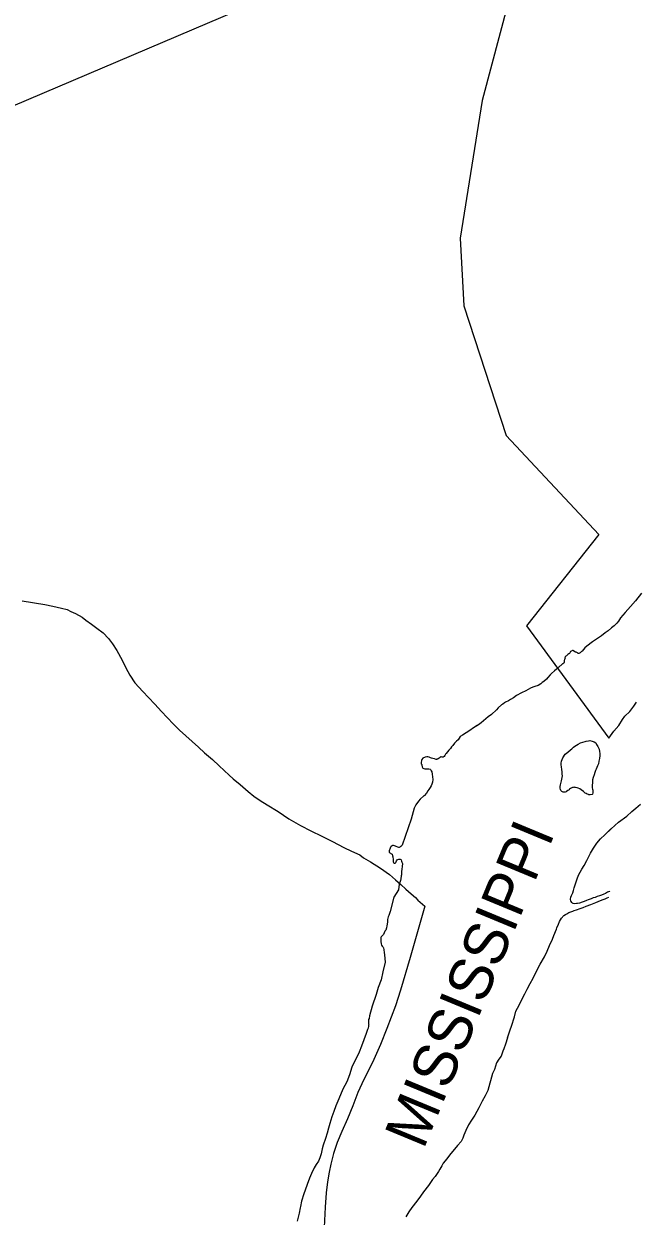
# Model space of a CAD drawing. Extents: x -117616 to 64730, y 54117 to 789866.
# Drawn here: x 62107.1 to 62196.9, y 55691.7 to 55866.6 of the extents above; entities that cross this region are included whole.
import ezdxf

# ---------------------------------------------------------------- set-up
doc = ezdxf.new("R2010")
doc.units = 0
for name, color, linetype in [('3', 7, 'Continuous'), ('9', 7, 'Continuous'), ('R_Draft', 7, 'Continuous')]:
    doc.layers.add(name, color=color, linetype=linetype)

msp = doc.modelspace()

# ---------------------------------------------------------------- linework, layer by layer
at = {"layer": '3'}
for points in [[(62179.37, 55874.54), (62174.3, 55855.4), (62171.05, 55835.19), (62171.61, 55825.27), (62177.79, 55806.26), (62191.41, 55791.73), (62180.77, 55778.33), (62192.85, 55761.85), (62193.58, 55762.86), (62194.3, 55763.69), (62194.87, 55764.57), (62195.19, 55765.06), (62195.93, 55765.76), (62196.51, 55766.52), (62196.91, 55767.09)], [(62106.85, 55781.99), (62110.15, 55781.44), (62111.35, 55781.19), (62112.64, 55780.92), (62113.44, 55780.69), (62113.99, 55780.42), (62114.67, 55780.11), (62115.66, 55779.58), (62116.2, 55779.16), (62117, 55778.55), (62117.82, 55777.97), (62118.72, 55777.27), (62119.52, 55776.46), (62120.08, 55775.67), (62120.73, 55774.68), (62121.5, 55773.29), (62122.03, 55772.14), (62122.62, 55771.07), (62123.38, 55769.97), (62124.54, 55768.67), (62125.35, 55767.82), (62126.31, 55766.84), (62127.3, 55765.76), (62128.12, 55764.86), (62129.04, 55763.88), (62129.92, 55763), (62132.68, 55760.5), (62133.59, 55759.67), (62134.76, 55758.69), (62135.73, 55757.79), (62137.19, 55756.42), (62137.8, 55755.87), (62138.8, 55755.03), (62139.97, 55754.02), (62140.83, 55753.33), (62141.73, 55752.69), (62142.76, 55752.05), (62144.4, 55751.05), (62145.95, 55749.99), (62147.64, 55749), (62149.16, 55748.23), (62150.8, 55747.45), (62152.34, 55746.69), (62154.02, 55745.81), (62155.15, 55745.27), (62156.33, 55744.69), (62156.89, 55744.28), (62157.93, 55743.68), (62159.37, 55742.76), (62160.68, 55741.83), (62161.59, 55741.03), (62162.37, 55740.34), (62163.12, 55739.68), (62163.87, 55739.01), (62164.5, 55738.47), (62164.87, 55738.04), (62165.87, 55737.16), (62163.72, 55729.66), (62162.33, 55724.87), (62161.6, 55722.56), (62160.29, 55719.22), (62159.36, 55716.9)], [(62159.36, 55716.9), (62158.22, 55714.26), (62156.92, 55711.77), (62156.04, 55709.83), (62155.34, 55707.88), (62154.52, 55705.97), (62153.72, 55704.11), (62153.04, 55702.5), (62152.49, 55700.89), (62152.1, 55699.34), (62151.85, 55698.16), (62151.62, 55696.73), (62151.43, 55695.1), (62151.25, 55693), (62151.11, 55690.09)]]:
    msp.add_lwpolyline(points, dxfattribs=at)
at = {"layer": '9'}
for points in [[(62197.65, 55783.09), (62196.78, 55781.99), (62196.03, 55781.13), (62195.27, 55780.27), (62194.59, 55779.49), (62194.26, 55779.02), (62194.01, 55778.69), (62193.92, 55778.6), (62193.63, 55778.31), (62193.24, 55778.03), (62192.77, 55777.6), (62192.32, 55777.28), (62191.76, 55776.86), (62191.04, 55776.36), (62190.48, 55775.97), (62189.62, 55775.35), (62189.36, 55775.09), (62189.14, 55774.83), (62188.95, 55774.62), (62188.87, 55774.55), (62188.79, 55774.48), (62188.67, 55774.37), (62188.48, 55774.26), (62188.45, 55774.26), (62188.37, 55774.27), (62188.33, 55774.27), (62188.24, 55774.34), (62188.14, 55774.4), (62188.07, 55774.43), (62187.98, 55774.46), (62187.87, 55774.52), (62187.68, 55774.63), (62187.61, 55774.67), (62187.56, 55774.68), (62187.55, 55774.69), (62187.43, 55774.64), (62187.36, 55774.61), (62187.24, 55774.54), (62187.2, 55774.46), (62187.13, 55774.33), (62187.08, 55774.26), (62187.07, 55774.26), (62186.99, 55774.2), (62186.86, 55774.1), (62186.74, 55774), (62186.63, 55773.92), (62186.53, 55773.84), (62186.43, 55773.75), (62186.42, 55773.67), (62186.43, 55773.6), (62186.42, 55773.47), (62186.38, 55773.37), (62186.35, 55773.31), (62186.32, 55773.24), (62186.32, 55773.16), (62186.31, 55773.06), (62186.29, 55772.96), (62186.25, 55772.83), (62186.13, 55772.75), (62186.01, 55772.68), (62185.54, 55772.26), (62185.42, 55772.18), (62185.2, 55771.97), (62184.89, 55771.71), (62184.45, 55771.3), (62184.27, 55771.1), (62183.92, 55770.71), (62183.7, 55770.49), (62183.34, 55770.16), (62183.1, 55770)], [(62183.1, 55770), (62182.88, 55769.82), (62182.5, 55769.57), (62182.02, 55769.42), (62181.73, 55769.32), (62181.36, 55769.17), (62180.67, 55768.79), (62180.07, 55768.5), (62179.34, 55768.08), (62178.86, 55767.77), (62178.42, 55767.49), (62178.13, 55767.33), (62177.73, 55767.11), (62177.54, 55767), (62177.32, 55766.83), (62177.14, 55766.7), (62176.64, 55766.28), (62176.38, 55766.01), (62175.66, 55765.32), (62175.19, 55764.94), (62174.15, 55764.09), (62173.77, 55763.78), (62173.01, 55763.37), (62172.46, 55762.96), (62171.38, 55762.27), (62171.06, 55762.08), (62170.77, 55761.59), (62170.54, 55761.4), (62170.25, 55761.11), (62169.98, 55760.78), (62169.79, 55760.54), (62169.62, 55760.34), (62169.42, 55760.08), (62169.21, 55759.82), (62168.99, 55759.59), (62168.9, 55759.46), (62168.79, 55759.27), (62168.7, 55759.15), (62168.57, 55759.06), (62168.51, 55759.05), (62168.42, 55759.06), (62168.27, 55759.07), (62168.26, 55759.07), (62168.22, 55759.07), (62168.19, 55759.04), (62168.14, 55759.02), (62168.06, 55758.98), (62168.01, 55758.96), (62167.97, 55758.91), (62167.82, 55758.8), (62167.75, 55758.77), (62167.66, 55758.73), (62167.58, 55758.69), (62167.54, 55758.72), (62167.32, 55758.8), (62167.03, 55758.86), (62166.84, 55758.91), (62166.69, 55758.97), (62166.53, 55759.05), (62166.32, 55759.1), (62166.19, 55759.09), (62165.95, 55759.05), (62165.81, 55759), (62165.67, 55758.94), (62165.61, 55758.89), (62165.45, 55758.7), (62165.38, 55758.54), (62165.34, 55758.25), (62165.35, 55758.09), (62165.42, 55757.95), (62165.43, 55757.82), (62165.47, 55757.72), (62165.51, 55757.62), (62165.55, 55757.51), (62165.61, 55757.41), (62165.74, 55757.36), (62165.87, 55757.33), (62166.05, 55757.32), (62166.19, 55757.31), (62166.32, 55757.31), (62166.47, 55757.32), (62166.66, 55757.29), (62166.73, 55757.22), (62166.77, 55757.15), (62166.82, 55757.05), (62166.9, 55756.88), (62166.94, 55756.54), (62166.99, 55756.14), (62167.04, 55755.77), (62167.02, 55755.38), (62166.93, 55755.07), (62166.81, 55754.86), (62166.65, 55754.61), (62166.49, 55754.3), (62166.34, 55754.08), (62166.12, 55753.76), (62165.77, 55753.37), (62165.75, 55753.35), (62165.22, 55752.89), (62164.94, 55752.59), (62164.54, 55752.06)], [(62173.57, 55763.67), (62173.01, 55763.37), (62172.46, 55762.96), (62171.38, 55762.27), (62171.06, 55762.08), (62170.77, 55761.59), (62170.54, 55761.4), (62170.25, 55761.11), (62169.98, 55760.78), (62169.79, 55760.54), (62169.62, 55760.34), (62169.42, 55760.08), (62169.21, 55759.82), (62168.99, 55759.59), (62168.9, 55759.46), (62168.79, 55759.27), (62168.7, 55759.15), (62168.57, 55759.06), (62168.51, 55759.05), (62168.42, 55759.06), (62168.27, 55759.07), (62168.26, 55759.07), (62168.22, 55759.07), (62168.19, 55759.04), (62168.14, 55759.02), (62168.06, 55758.98), (62168.01, 55758.96), (62167.97, 55758.91), (62167.82, 55758.8), (62167.75, 55758.77), (62167.66, 55758.73), (62167.58, 55758.69), (62167.54, 55758.72), (62167.32, 55758.8), (62167.03, 55758.86), (62166.84, 55758.91), (62166.69, 55758.97), (62166.53, 55759.05), (62166.32, 55759.1), (62166.19, 55759.09), (62165.95, 55759.05), (62165.81, 55759), (62165.67, 55758.94), (62165.61, 55758.89), (62165.45, 55758.7), (62165.38, 55758.54), (62165.34, 55758.25), (62165.35, 55758.09), (62165.42, 55757.95), (62165.43, 55757.82), (62165.47, 55757.72), (62165.51, 55757.62), (62165.55, 55757.51), (62165.61, 55757.41), (62165.74, 55757.36), (62165.87, 55757.33), (62166.05, 55757.32), (62166.19, 55757.31), (62166.32, 55757.31), (62166.47, 55757.32), (62166.66, 55757.29), (62166.73, 55757.22), (62166.77, 55757.15), (62166.82, 55757.05), (62166.9, 55756.88), (62166.94, 55756.54), (62166.99, 55756.14), (62167.04, 55755.77), (62167.02, 55755.38), (62166.93, 55755.07), (62166.81, 55754.86), (62166.65, 55754.61), (62166.49, 55754.3), (62166.34, 55754.08), (62166.12, 55753.76), (62165.77, 55753.37), (62165.75, 55753.35), (62165.22, 55752.89), (62164.94, 55752.59), (62164.54, 55752.06)], [(62185.86, 55757.95), (62185.85, 55758.18), (62185.92, 55758.45), (62186.1, 55758.95), (62186.45, 55759.48), (62186.85, 55759.79), (62187.25, 55760.12), (62187.41, 55760.27), (62187.7, 55760.49), (62187.89, 55760.65), (62188.38, 55760.96), (62188.7, 55761.14), (62189.02, 55761.25), (62189.38, 55761.35), (62189.51, 55761.38), (62189.87, 55761.46), (62190.08, 55761.47), (62190.39, 55761.41), (62190.72, 55761.3), (62190.97, 55761.15), (62191.07, 55760.9), (62191.25, 55760.61), (62191.42, 55760.24), (62191.51, 55759.89), (62191.55, 55759.6), (62191.53, 55759.28), (62191.47, 55758.86), (62191.4, 55758.45), (62191.32, 55758.09), (62191.19, 55757.76), (62190.99, 55757.3), (62190.9, 55757.09), (62190.79, 55756.78), (62190.7, 55756.44), (62190.56, 55756.07), (62190.48, 55755.7), (62190.45, 55755.31), (62190.43, 55754.89), (62190.43, 55754.55), (62190.45, 55754.36), (62190.49, 55754.2), (62190.53, 55753.99), (62190.53, 55753.82), (62190.47, 55753.63), (62190.39, 55753.57), (62190.14, 55753.53), (62189.92, 55753.54), (62189.87, 55753.55), (62189.67, 55753.62), (62189.51, 55753.69), (62189.37, 55753.77), (62189.28, 55753.87), (62189.16, 55754), (62188.81, 55754.27), (62188.61, 55754.38), (62188.36, 55754.49), (62188.2, 55754.53), (62187.96, 55754.59), (62187.85, 55754.61), (62187.77, 55754.62), (62187.65, 55754.59), (62187.51, 55754.57), (62187.45, 55754.54), (62187.33, 55754.5), (62187.25, 55754.45), (62187.11, 55754.34), (62187.02, 55754.24), (62186.86, 55754.15), (62186.67, 55754.02), (62186.58, 55753.97), (62186.45, 55753.93), (62186.28, 55753.91), (62186.16, 55753.93), (62185.96, 55754.02), (62185.88, 55754.09), (62185.82, 55754.17), (62185.78, 55754.29), (62185.72, 55754.51), (62185.71, 55754.72), (62185.77, 55754.98), (62185.82, 55755.2)], [(62185.82, 55755.2), (62185.92, 55755.55), (62185.98, 55755.82), (62186.04, 55756.3), (62186.03, 55756.53), (62186.02, 55756.83), (62185.97, 55757.27), (62185.93, 55757.56), (62185.86, 55757.95)], [(62164.54, 55752.06), (62164.34, 55751.55), (62163.88, 55749.93), (62162.54, 55746.13), (62162.47, 55746.05), (62162.36, 55745.95), (62162.33, 55745.92), (62162.28, 55745.87), (62162.2, 55745.82), (62162.12, 55745.8), (62162.05, 55745.8), (62161.91, 55745.85), (62161.69, 55745.93), (62161.57, 55745.98), (62161.41, 55746.03), (62161.28, 55746.08), (62161.16, 55746.07), (62161.08, 55746.03), (62160.93, 55745.95), (62160.84, 55745.84), (62160.78, 55745.69), (62160.73, 55745.55), (62160.69, 55745.43), (62160.65, 55745.32), (62160.63, 55745.2), (62160.66, 55745.11), (62160.77, 55745.02), (62160.84, 55744.97), (62160.9, 55744.93), (62161, 55744.85), (62161.07, 55744.8), (62161.12, 55744.59), (62161.18, 55744.44), (62161.2, 55744.3), (62161.24, 55744.13), (62161.25, 55744.01), (62161.25, 55743.89), (62161.24, 55743.79), (62161.26, 55743.68), (62161.3, 55743.57), (62161.32, 55743.52), (62161.35, 55743.48), (62161.4, 55743.48), (62161.47, 55743.47), (62161.52, 55743.5), (62161.56, 55743.55), (62161.61, 55743.61), (62161.66, 55743.69), (62161.73, 55743.81), (62161.83, 55743.96), (62161.93, 55744.04), (62162.05, 55744.1), (62162.15, 55744.09), (62162.26, 55744.08), (62162.34, 55744.03), (62162.39, 55743.96), (62162.44, 55743.8), (62162.53, 55743.63), (62162.59, 55743.43), (62162.58, 55742.98), (62162.53, 55742.6), (62162.48, 55742.27), (62162.46, 55741.79), (62162.42, 55741.63), (62162.34, 55741.21), (62162.32, 55740.95), (62162.27, 55740.79), (62162.17, 55740.54), (62162.1, 55740.41), (62162, 55739.59), (62161.32, 55738.5), (62160.8, 55736.42), (62160.62, 55735.82), (62160.53, 55735.61), (62160.43, 55735.21), (62160.39, 55734.89), (62160.36, 55734.54), (62160.33, 55734.3), (62160.25, 55733.98), (62160.14, 55733.66), (62160.03, 55733.5), (62159.93, 55733.26), (62159.81, 55733.04), (62159.71, 55732.93), (62159.62, 55732.83), (62159.5, 55732.67), (62159.44, 55732.57), (62159.41, 55732.49), (62159.42, 55732.25), (62159.42, 55731.99), (62159.49, 55731.67), (62159.55, 55731.47), (62159.63, 55731.3), (62159.76, 55731.16), (62159.84, 55731.05), (62159.88, 55730.78), (62159.93, 55730.36), (62159.96, 55730.06), (62160.06, 55728.97), (62159.74, 55727.55), (62159.46, 55726.36)], [(62164.54, 55752.06), (62164.34, 55751.55), (62163.88, 55749.93), (62162.54, 55746.13), (62162.47, 55746.05), (62162.36, 55745.95), (62162.33, 55745.92), (62162.28, 55745.87), (62162.2, 55745.82), (62162.12, 55745.8), (62162.05, 55745.8), (62161.91, 55745.85), (62161.69, 55745.93), (62161.57, 55745.98), (62161.41, 55746.03), (62161.28, 55746.08), (62161.16, 55746.07), (62161.08, 55746.03), (62160.93, 55745.95), (62160.84, 55745.84), (62160.78, 55745.69), (62160.73, 55745.55), (62160.69, 55745.43), (62160.65, 55745.32), (62160.63, 55745.2), (62160.66, 55745.11), (62160.77, 55745.02), (62160.84, 55744.97), (62160.9, 55744.93), (62161, 55744.85), (62161.07, 55744.8), (62161.12, 55744.59), (62161.18, 55744.44), (62161.2, 55744.3), (62161.24, 55744.13), (62161.25, 55744.01), (62161.25, 55743.89), (62161.24, 55743.79), (62161.26, 55743.68), (62161.3, 55743.57), (62161.32, 55743.52), (62161.35, 55743.48), (62161.4, 55743.48), (62161.47, 55743.47), (62161.52, 55743.5), (62161.56, 55743.55), (62161.61, 55743.61), (62161.66, 55743.69), (62161.73, 55743.81), (62161.83, 55743.96), (62161.93, 55744.04), (62162.05, 55744.1), (62162.15, 55744.09), (62162.26, 55744.08), (62162.34, 55744.03), (62162.39, 55743.96), (62162.44, 55743.8), (62162.53, 55743.63), (62162.59, 55743.43), (62162.58, 55742.98), (62162.53, 55742.6), (62162.48, 55742.27), (62162.46, 55741.79), (62162.42, 55741.63), (62162.34, 55741.21), (62162.32, 55740.95), (62162.27, 55740.79), (62162.17, 55740.54), (62162.1, 55740.41), (62162, 55739.59), (62161.32, 55738.5), (62160.8, 55736.42), (62160.62, 55735.82), (62160.53, 55735.61), (62160.43, 55735.21), (62160.39, 55734.89), (62160.36, 55734.54), (62160.33, 55734.3), (62160.25, 55733.98), (62160.14, 55733.66), (62160.03, 55733.5), (62159.93, 55733.26), (62159.81, 55733.04), (62159.71, 55732.93), (62159.62, 55732.83), (62159.5, 55732.67), (62159.44, 55732.57), (62159.41, 55732.49), (62159.42, 55732.25), (62159.42, 55731.99), (62159.49, 55731.67), (62159.55, 55731.47), (62159.63, 55731.3), (62159.76, 55731.16), (62159.84, 55731.05), (62159.88, 55730.78), (62159.93, 55730.36), (62159.96, 55730.06), (62160.06, 55728.97), (62159.74, 55727.55), (62159.46, 55726.36)], [(62193, 55739.4), (62192.96, 55739.34), (62192.66, 55739.22), (62192.37, 55739.06), (62192.14, 55738.94), (62191.78, 55738.8), (62191.47, 55738.69), (62191.15, 55738.59), (62190.83, 55738.46), (62190.57, 55738.39), (62190.26, 55738.27), (62189.85, 55738.1), (62189.58, 55738.01), (62189.24, 55737.89), (62188.95, 55737.79), (62188.56, 55737.64), (62188.27, 55737.58), (62188.1, 55737.55), (62187.84, 55737.53), (62187.64, 55737.59), (62187.53, 55737.64), (62187.41, 55737.74), (62187.32, 55737.85), (62187.3, 55737.94), (62187.26, 55738.21), (62187.28, 55738.48), (62187.39, 55738.74), (62187.56, 55739.13), (62187.67, 55739.48), (62187.77, 55739.86), (62188.19, 55741.19), (62188.4, 55741.71), (62188.92, 55742.63), (62189.24, 55743.16), (62189.61, 55743.9), (62189.91, 55744.49), (62190.19, 55744.98), (62190.6, 55745.69), (62191.11, 55746.44), (62191.63, 55747.04), (62192.27, 55747.66), (62193.19, 55748.55), (62194.28, 55749.49), (62195.48, 55750.4), (62196.25, 55751.06), (62196.81, 55751.55), (62197.48, 55752.15)], [(62193, 55739.4), (62192.96, 55739.34), (62192.66, 55739.22), (62192.37, 55739.06), (62192.14, 55738.94), (62191.78, 55738.8), (62191.47, 55738.69), (62191.15, 55738.59), (62190.83, 55738.46), (62190.57, 55738.39), (62190.26, 55738.27), (62189.85, 55738.1), (62189.58, 55738.01), (62189.24, 55737.89), (62188.95, 55737.79), (62188.56, 55737.64), (62188.27, 55737.58), (62188.1, 55737.55), (62187.84, 55737.53), (62187.64, 55737.59), (62187.53, 55737.64), (62187.41, 55737.74), (62187.32, 55737.85), (62187.3, 55737.94), (62187.26, 55738.21), (62187.28, 55738.48), (62187.39, 55738.74), (62187.56, 55739.13), (62187.67, 55739.48), (62187.77, 55739.86), (62188.19, 55741.19), (62188.4, 55741.71), (62188.92, 55742.63), (62189.24, 55743.16), (62189.61, 55743.9), (62189.91, 55744.49), (62190.19, 55744.98), (62190.6, 55745.69), (62191.11, 55746.44), (62191.63, 55747.04), (62192.27, 55747.66), (62193.14, 55748.51)], [(62178.02, 55717.85), (62178.41, 55719.05), (62178.58, 55719.59), (62179.02, 55720.96), (62179.22, 55721.79), (62179.7, 55722.66), (62179.93, 55723.09), (62180.56, 55724.3), (62180.9, 55725.02), (62181.31, 55725.85), (62181.75, 55726.61), (62182.19, 55727.57), (62182.78, 55728.65), (62183.4, 55729.77), (62183.81, 55730.59), (62184.18, 55731.39), (62184.59, 55732.34), (62184.8, 55732.86), (62185.16, 55733.83), (62185.23, 55734), (62185.46, 55734.56), (62185.61, 55734.91), (62185.76, 55735.19), (62185.91, 55735.42), (62186.04, 55735.57), (62186.13, 55735.68), (62186.27, 55735.83), (62186.49, 55735.95), (62186.71, 55736.08), (62187.01, 55736.23), (62187.41, 55736.38), (62187.56, 55736.45), (62187.78, 55736.55), (62188.13, 55736.66), (62188.64, 55736.82), (62189.1, 55737), (62189.51, 55737.16), (62190.22, 55737.41), (62190.95, 55737.72), (62191.61, 55737.99), (62192.02, 55738.17), (62192.34, 55738.28), (62192.62, 55738.4), (62192.85, 55738.52)], [(62178.02, 55717.85), (62178.41, 55719.05), (62178.58, 55719.59), (62179.02, 55720.96), (62179.22, 55721.79), (62179.7, 55722.66), (62179.93, 55723.09), (62180.56, 55724.3), (62180.9, 55725.02), (62181.31, 55725.85), (62181.75, 55726.61), (62182.19, 55727.57), (62182.78, 55728.65), (62183.4, 55729.77), (62183.81, 55730.59), (62184.18, 55731.39), (62184.59, 55732.34), (62184.8, 55732.86), (62185.16, 55733.83), (62185.23, 55734), (62185.46, 55734.56), (62185.61, 55734.91), (62185.76, 55735.19), (62185.91, 55735.42), (62186.04, 55735.57), (62186.13, 55735.68), (62186.27, 55735.83), (62186.49, 55735.95), (62186.71, 55736.08), (62187.01, 55736.23), (62187.41, 55736.38), (62187.56, 55736.45), (62187.78, 55736.55), (62188.13, 55736.66), (62188.64, 55736.82), (62189.1, 55737), (62189.51, 55737.16), (62190.22, 55737.41), (62190.95, 55737.72), (62191.61, 55737.99), (62192.02, 55738.17), (62192.34, 55738.28), (62192.62, 55738.4), (62192.85, 55738.52)], [(62159.46, 55726.36), (62159.03, 55725.25), (62158.75, 55724.24), (62158.18, 55722.5), (62157.78, 55721.07), (62157.7, 55720.72), (62157.64, 55720.53), (62157.64, 55720.41), (62157.63, 55720.31), (62157.63, 55720.15), (62157.64, 55720.05), (62157.64, 55719.98), (62157.65, 55719.87), (62157.64, 55719.75), (62157.62, 55719.59), (62157.55, 55719.3), (62157.47, 55719.11), (62157.27, 55718.48), (62156.61, 55716.62)], [(62159.46, 55726.36), (62159.03, 55725.25), (62158.75, 55724.24), (62158.18, 55722.5), (62157.78, 55721.07), (62157.7, 55720.72), (62157.64, 55720.53), (62157.64, 55720.41), (62157.63, 55720.31), (62157.63, 55720.15), (62157.64, 55720.05), (62157.64, 55719.98), (62157.65, 55719.87), (62157.64, 55719.75), (62157.62, 55719.59), (62157.55, 55719.3), (62157.47, 55719.11), (62157.27, 55718.48), (62156.61, 55716.62)], [(62178.02, 55717.85), (62177.73, 55716.94), (62177.44, 55716.25), (62177.32, 55715.93), (62177.08, 55715.19), (62176.75, 55714.72), (62176.37, 55714.19), (62176.1, 55713.23), (62175.82, 55712.62), (62175.1, 55710.16), (62174.71, 55709.34), (62174.3, 55708.55), (62173.8, 55707.58), (62173.23, 55706.53), (62172.73, 55705.77), (62172.3, 55705.1), (62171.89, 55704.28), (62171.59, 55703.59), (62171.44, 55703.13), (62171.23, 55702.65), (62170.68, 55702.07), (62169.5, 55700.63), (62169.11, 55700.11), (62168.59, 55699.48), (62168.36, 55699.1), (62168.06, 55698.58), (62167.9, 55698.25), (62167.71, 55697.95), (62167.4, 55697.54), (62166.99, 55697.1), (62166.41, 55696.22), (62165.7, 55695.28), (62165.23, 55694.65), (62164.69, 55693.92), (62163.99, 55692.96), (62163.56, 55692.34), (62163.08, 55691.62)], [(62156.61, 55716.62), (62156.25, 55715.76), (62156.04, 55715.31), (62155.68, 55714.61), (62155.17, 55713.55), (62154.82, 55712.45), (62154.44, 55711.43), (62153.87, 55710.32), (62153.52, 55709.52), (62153.13, 55708.59), (62152.82, 55707.9), (62152.52, 55707.07), (62152.27, 55706.25), (62151.94, 55705.29), (62151.77, 55704.62), (62151.57, 55703.87), (62151.33, 55703.1), (62151, 55702.13), (62150.85, 55701.56), (62150.69, 55700.82), (62150.51, 55700.25), (62150.28, 55699.78), (62149.96, 55699.29), (62149.66, 55698.8), (62149.25, 55697.98), (62148.98, 55697.27), (62148.63, 55696.36), (62148.33, 55695.53), (62148.12, 55694.96), (62147.81, 55693.89), (62147.65, 55693.14), (62147.59, 55692.92), (62147.44, 55692.13), (62147.17, 55690.96)]]:
    msp.add_lwpolyline(points, dxfattribs=at)
at = {"layer": 'R_Draft'}
msp.add_line((61948.13, 55787.58), (62377.34, 55970.42), dxfattribs=at)

# ---------------------------------------------------------------- texts
at = {"layer": '9'}
msp.add_text('MISSISSIPPI', height=6.336, rotation=67.4553, dxfattribs=at).set_placement((62165.68, 55701.36))

doc.saveas('drawing.dxf')
